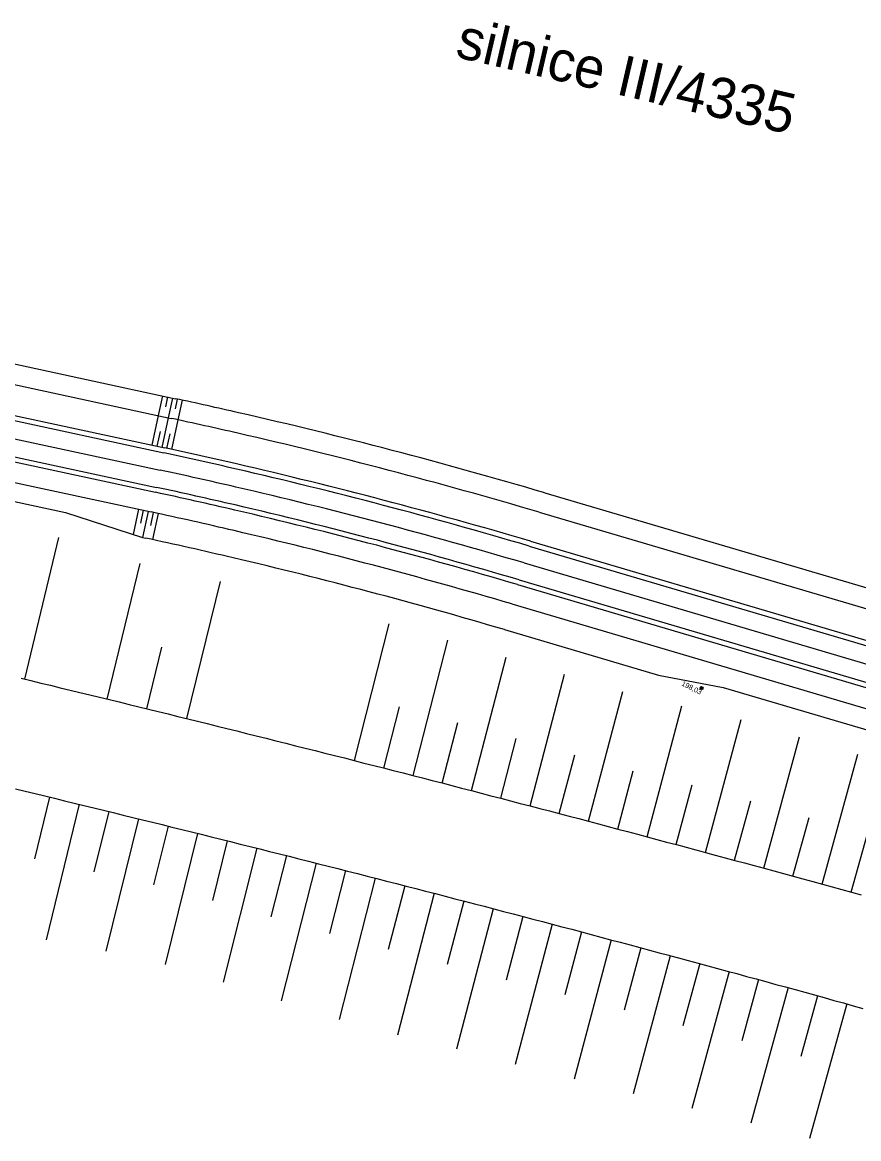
# Model space of a CAD drawing. Extents: x -552278 to -547230, y -1151007 to -1148251.
# Drawn here: x -551031.8 to -550948.8, y -1148768.4 to -1148657.6 of the extents above; entities that cross this region are included whole.
import ezdxf

# ---------------------------------------------------------------- set-up
doc = ezdxf.new("R2010")
doc.units = 0
for name, color, linetype in [('SO221815_VYSKOPIS', 7, 'Continuous'), ('u_popis_stavajici', 7, 'Continuous'), ('u_trat navrh', 7, 'Continuous')]:
    doc.layers.add(name, color=color, linetype=linetype)

# ---------------------------------------------------------------- blocks, each defined once
blk = doc.blocks.new('SO221824_VYSKOPIS')
at = {"layer": 'SO221815_VYSKOPIS'}
for p, q in [((1.2, -0.9), (-1.2, 0.9)), ((0.9, 1.2), (-0.9, -1.2)), ((0.9, 1.2), (0, 0)), ((0, 0), (1.2, -0.9))]:
    blk.add_line(p, q, dxfattribs=at)
blk.add_lwpolyline([(-0.9, -1.2), (0, 0), (-1.2, 0.9)], dxfattribs=at)
blk.add_circle((0, 0), 1.5, dxfattribs=at)
for start, end in [(145.362, 235.1538), (325.362, 55.1538)]:
    blk.add_arc((0, 0), 1.5, start, end, dxfattribs=at)

msp = doc.modelspace()

# ---------------------------------------------------------------- linework, layer by layer
at = {"layer": 'u_trat navrh'}
for p, q in [((-551123.53, -1148671.88), (-551016.54, -1148694.95)), ((-551124.05, -1148673.81), (-551016.97, -1148696.91)), ((-551122.37, -1148677.24), (-551017.6, -1148699.84)), ((-551128.73, -1148678.17), (-551018.07, -1148702.04)), ((-551122.5, -1148677.73), (-551017.7, -1148700.33)), ((-551144.49, -1148681.02), (-551027.47, -1148706.25)), ((-551123.32, -1148681.64), (-551018.55, -1148704.24)), ((-551123.24, -1148681.15), (-551018.44, -1148703.75)), ((-551123.74, -1148683.6), (-551018.97, -1148706.19)), ((-551018.23, -1148696.63), (-551017.81, -1148694.68)), ((-551017.53, -1148695.76), (-551017.32, -1148694.78)), ((-551017.26, -1148696.84), (-551016.83, -1148694.89)), ((-551016.56, -1148695.97), (-551016.35, -1148694.99)), ((-551016.28, -1148697.05), (-551015.86, -1148695.1)), ((-551018.87, -1148699.57), (-551018.23, -1148696.63)), ((-551017.89, -1148699.78), (-551017.26, -1148696.84)), ((-551016.91, -1148699.99), (-551016.28, -1148697.05)), ((-551018.38, -1148699.67), (-551018.06, -1148698.2)), ((-551017.4, -1148699.88), (-551017.08, -1148698.42)), ((-550979.91, -1148704.29), (-550939.15, -1148716.32)), ((-551020.24, -1148705.92), (-551020.77, -1148708.41)), ((-551019.75, -1148706.02), (-551020.02, -1148707.3)), ((-551019.26, -1148706.13), (-551019.82, -1148708.72)), ((-551027.47, -1148706.25), (-551019.82, -1148708.72)), ((-551018.77, -1148706.24), (-551019.05, -1148707.53)), ((-551018.28, -1148706.34), (-551018.84, -1148708.93)), ((-550980.48, -1148706.21), (-550939.72, -1148718.24)), ((-551031.5, -1148722.78), (-551028.13, -1148708.73)), ((-551019.82, -1148708.72), (-551019.53, -1148708.78)), ((-550981.33, -1148709.09), (-550940.56, -1148721.12)), ((-550981.47, -1148709.57), (-550940.71, -1148721.6)), ((-551023.34, -1148724.75), (-551020.07, -1148711.29)), ((-550981.97, -1148711.25), (-550909.55, -1148732.61)), ((-551015.44, -1148726.69), (-551012.09, -1148713.08)), ((-550982.6, -1148713.4), (-550910.19, -1148734.77)), ((-550982.46, -1148712.92), (-550910.05, -1148734.29)), ((-550983.17, -1148715.32), (-550910.76, -1148736.69)), ((-550998.8, -1148730.86), (-550995.35, -1148717.29)), ((-550983.92, -1148717.86), (-550968.63, -1148722.37)), ((-550992.98, -1148732.34), (-550989.53, -1148718.9)), ((-551019.39, -1148725.72), (-551017.9, -1148719.62)), ((-550987.17, -1148733.84), (-550983.74, -1148720.59)), ((-550981.37, -1148735.35), (-550977.96, -1148722.29)), ((-550968.63, -1148722.37), (-550962.22, -1148723.59)), ((-550962.22, -1148723.59), (-550920.49, -1148735.9)), ((-550975.56, -1148736.88), (-550972.16, -1148724)), ((-550995.89, -1148731.6), (-550994.34, -1148725.52)), ((-550969.76, -1148738.42), (-550966.3, -1148725.42)), ((-550990.08, -1148733.09), (-550988.53, -1148727.08)), ((-550963.96, -1148739.97), (-550960.41, -1148726.79)), ((-550984.28, -1148734.59), (-550982.74, -1148728.67)), ((-550958.17, -1148741.54), (-550954.63, -1148728.5)), ((-550978.47, -1148736.11), (-550976.93, -1148730.28)), ((-550952.38, -1148743.12), (-550948.84, -1148730.21)), ((-550972.66, -1148737.65), (-550971.13, -1148731.89)), ((-550966.86, -1148739.19), (-550965.27, -1148733.25)), ((-551029.07, -1148734.48), (-551030.55, -1148740.62)), ((-550961.07, -1148740.75), (-550959.47, -1148734.85)), ((-551026.12, -1148735.19), (-551029.4, -1148748.65)), ((-551023.18, -1148735.91), (-551024.65, -1148741.89)), ((-551020.24, -1148736.63), (-551023.47, -1148749.77)), ((-550955.28, -1148742.33), (-550953.68, -1148736.49)), ((-551017.3, -1148737.35), (-551018.75, -1148743.2)), ((-551014.36, -1148738.08), (-551017.59, -1148751.1)), ((-550949.49, -1148743.92), (-550947.89, -1148738.13)), ((-551011.42, -1148738.81), (-551012.9, -1148744.74)), ((-551008.49, -1148739.55), (-551011.83, -1148752.86)), ((-551005.55, -1148740.29), (-551007.08, -1148746.36)), ((-551002.61, -1148741.03), (-551006.08, -1148754.69)), ((-550999.68, -1148741.78), (-551001.27, -1148748.01)), ((-550996.75, -1148742.53), (-551000.33, -1148756.54)), ((-550993.81, -1148743.28), (-550995.44, -1148749.62)), ((-550990.88, -1148744.03), (-550994.52, -1148758.11)), ((-550987.95, -1148744.8), (-550989.59, -1148751.1)), ((-550985.02, -1148745.56), (-550988.66, -1148759.5)), ((-550982.09, -1148746.33), (-550983.75, -1148752.66)), ((-550979.17, -1148747.09), (-550982.84, -1148761)), ((-550976.28, -1148747.86), (-550977.93, -1148754.09)), ((-550973.31, -1148748.65), (-550976.99, -1148762.46)), ((-550970.38, -1148749.43), (-550972.04, -1148755.62)), ((-550967.46, -1148750.22), (-550971.15, -1148763.91)), ((-550964.53, -1148751), (-550966.2, -1148757.18)), ((-550961.61, -1148751.8), (-550965.31, -1148765.39)), ((-550958.69, -1148752.59), (-550960.35, -1148758.66)), ((-550955.77, -1148753.39), (-550959.45, -1148766.82)), ((-550952.85, -1148754.19), (-550954.51, -1148760.23)), ((-550949.93, -1148755), (-550953.63, -1148768.37))]:
    msp.add_line(p, q, dxfattribs=at)
for points in [[(-551031.88, -1148722.69), (-551030.91, -1148722.92), (-551029.93, -1148723.16), (-551028.96, -1148723.39), (-551027.99, -1148723.63), (-551027.01, -1148723.86), (-551026.04, -1148724.1), (-551025.07, -1148724.33), (-551024.09, -1148724.57), (-551023.12, -1148724.81), (-551022.15, -1148725.04), (-551021.17, -1148725.28), (-551020.2, -1148725.52), (-551019.23, -1148725.76), (-551018.26, -1148726), (-551017.28, -1148726.23), (-551016.31, -1148726.47), (-551015.34, -1148726.71), (-551014.37, -1148726.95), (-551013.4, -1148727.19), (-551012.42, -1148727.43), (-551011.45, -1148727.68), (-551010.48, -1148727.92), (-551009.51, -1148728.16), (-551008.54, -1148728.4), (-551007.56, -1148728.65), (-551006.59, -1148728.89), (-551005.62, -1148729.13), (-551004.65, -1148729.38), (-551003.68, -1148729.62), (-551002.71, -1148729.87), (-551001.74, -1148730.11), (-551000.77, -1148730.36), (-550999.8, -1148730.6), (-550998.83, -1148730.85), (-550997.86, -1148731.1), (-550996.89, -1148731.34), (-550995.92, -1148731.59), (-550994.94, -1148731.84), (-550993.97, -1148732.09), (-550993, -1148732.33), (-550992.03, -1148732.58), (-550991.07, -1148732.83), (-550990.1, -1148733.08), (-550989.13, -1148733.33), (-550988.16, -1148733.58), (-550987.19, -1148733.83), (-550986.22, -1148734.09), (-550985.25, -1148734.34), (-550984.28, -1148734.59), (-550983.31, -1148734.84), (-550982.34, -1148735.1), (-550981.37, -1148735.35), (-550980.4, -1148735.6), (-550979.44, -1148735.86), (-550978.47, -1148736.11), (-550977.5, -1148736.37), (-550976.53, -1148736.62), (-550975.56, -1148736.88), (-550974.59, -1148737.13), (-550973.63, -1148737.39), (-550972.66, -1148737.65), (-550971.69, -1148737.9), (-550970.72, -1148738.16), (-550969.76, -1148738.42), (-550968.79, -1148738.68), (-550967.82, -1148738.94), (-550966.85, -1148739.2), (-550965.89, -1148739.45), (-550964.92, -1148739.71), (-550964.43, -1148739.85), (-550963.95, -1148739.97), (-550962.99, -1148740.24), (-550962.02, -1148740.5), (-550961.05, -1148740.76), (-550960.09, -1148741.02), (-550959.12, -1148741.28), (-550958.15, -1148741.54), (-550957.19, -1148741.81), (-550956.22, -1148742.07), (-550955.25, -1148742.33), (-550954.29, -1148742.6), (-550953.32, -1148742.86), (-550952.36, -1148743.13), (-550951.39, -1148743.39), (-550950.43, -1148743.66), (-550949.46, -1148743.93), (-550948.5, -1148744.19)], [(-551032.44, -1148733.66), (-551031.47, -1148733.9), (-551030.49, -1148734.13), (-551029.52, -1148734.37), (-551028.55, -1148734.6), (-551027.58, -1148734.84), (-551026.61, -1148735.07), (-551025.64, -1148735.31), (-551024.67, -1148735.54), (-551023.7, -1148735.78), (-551022.73, -1148736.02), (-551021.76, -1148736.26), (-551020.79, -1148736.49), (-551019.82, -1148736.73), (-551018.85, -1148736.97), (-551017.88, -1148737.21), (-551016.91, -1148737.45), (-551015.94, -1148737.69), (-551014.97, -1148737.93), (-551014, -1148738.17), (-551013.03, -1148738.41), (-551012.07, -1148738.65), (-551011.1, -1148738.89), (-551010.13, -1148739.14), (-551009.16, -1148739.38), (-551008.19, -1148739.62), (-551007.22, -1148739.87), (-551006.25, -1148740.11), (-551005.28, -1148740.35), (-551004.32, -1148740.6), (-551003.35, -1148740.84), (-551002.38, -1148741.09), (-551001.41, -1148741.33), (-551000.44, -1148741.58), (-550999.48, -1148741.83), (-550998.51, -1148742.07), (-550997.54, -1148742.32), (-550996.57, -1148742.57), (-550995.61, -1148742.82), (-550994.64, -1148743.07), (-550993.67, -1148743.31), (-550992.7, -1148743.56), (-550991.74, -1148743.81), (-550990.77, -1148744.06), (-550989.8, -1148744.31), (-550988.84, -1148744.56), (-550987.87, -1148744.82), (-550986.9, -1148745.07), (-550985.94, -1148745.32), (-550984.97, -1148745.57), (-550984, -1148745.82), (-550983.04, -1148746.08), (-550982.07, -1148746.33), (-550981.11, -1148746.58), (-550980.14, -1148746.84), (-550979.17, -1148747.09), (-550978.21, -1148747.35), (-550977.24, -1148747.6), (-550976.28, -1148747.86), (-550975.31, -1148748.12), (-550974.35, -1148748.37), (-550973.38, -1148748.63), (-550972.42, -1148748.89), (-550971.45, -1148749.14), (-550970.49, -1148749.4), (-550969.52, -1148749.66), (-550968.56, -1148749.92), (-550967.59, -1148750.18), (-550967.53, -1148750.2), (-550966.63, -1148750.44), (-550965.67, -1148750.7), (-550964.7, -1148750.96), (-550963.74, -1148751.22), (-550962.77, -1148751.48), (-550961.81, -1148751.74), (-550960.85, -1148752), (-550959.88, -1148752.27), (-550958.92, -1148752.53), (-550957.96, -1148752.79), (-550956.99, -1148753.06), (-550956.03, -1148753.32), (-550955.07, -1148753.58), (-550954.1, -1148753.85), (-550953.14, -1148754.11), (-550952.18, -1148754.38), (-550951.21, -1148754.65), (-550950.25, -1148754.91), (-550949.29, -1148755.18), (-550948.33, -1148755.45)]]:
    msp.add_lwpolyline(points, dxfattribs=at)
for radius, start, end in [(507.25, 77.1071, 77.8299), (505.25, 77.0641, 77.8299), (507.25, 73.559, 77.1071), (505.25, 73.559, 77.0641), (501.75, 76.9876, 77.8299), (502.25, 76.9988, 77.8299), (502.25, 73.559, 76.9988), (500, 76.9491, 77.8299), (501.75, 73.559, 76.9876), (498.25, 76.9104, 77.8299), (500, 73.559, 76.9491), (497.75, 76.8993, 77.8299), (495.75, 76.8546, 77.8299), (497.75, 73.559, 76.8993), (498.25, 73.559, 76.9104), (495.75, 73.559, 76.8546), (493.1, 76.7949, 77.8299), (493.1, 73.559, 76.7949)]:
    msp.add_arc((-551123.48, -1149190.8), radius, start, end, dxfattribs=at)

# ---------------------------------------------------------------- block references
at = {"layer": 'u_trat navrh', "xscale": 0.1, "yscale": 0.09999999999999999, "rotation": -31.851985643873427}
msp.add_blockref('SO221824_VYSKOPIS', (-550964.35, -1148723.67), dxfattribs=at)

# ---------------------------------------------------------------- texts
at = {"layer": 'u_popis_stavajici'}
msp.add_text('silnice III/4335', height=4, rotation=346.9655, dxfattribs=at).set_placement((-550988.89, -1148661.02))
at = {"layer": 'u_trat navrh'}
msp.add_text('198,03', height=0.5, rotation=333.2568, dxfattribs=at).set_placement((-550966.38, -1148723.38))

doc.saveas('drawing.dxf')
